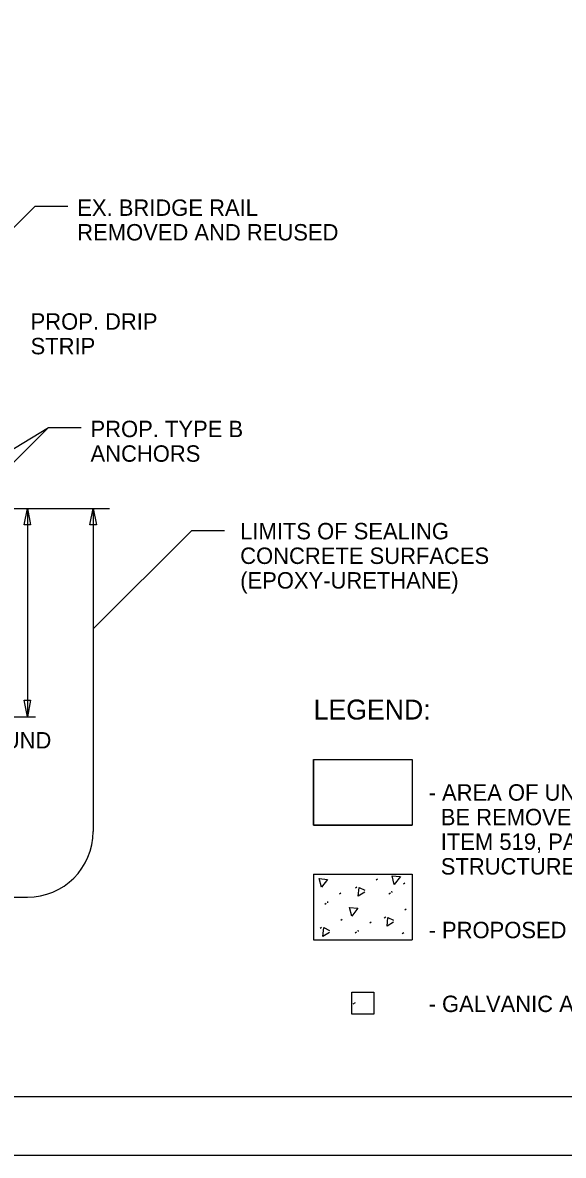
# Model space of a CAD drawing. Extents: x -2063 to 2068, y 79 to 1202.
# Drawn here: x -530.87 to -507.83, y 242.47 to 290.78 of the extents above; entities that cross this region are included whole.
import ezdxf

# ---------------------------------------------------------------- set-up
doc = ezdxf.new("R2010")
doc.units = 0
for name, color, linetype in [('BR_P_Gen_Text', 7, 'Continuous'), ('BR_P_Gen_Utilities', 7, 'Continuous'), ('Default', 7, 'Continuous'), ('SH_Border', 7, 'Continuous'), ('SH_Cut_Line', 7, 'Continuous'), ('SH_Text', 7, 'Continuous')]:
    doc.layers.add(name, color=color, linetype=linetype)

msp = doc.modelspace()

# ---------------------------------------------------------------- linework, layer by layer
at = {"layer": 'BR_P_Gen_Text'}
for p, q in [((-532.738, 270.052), (-527.168, 270.052)), ((-530.668, 270.052), (-530.668, 261.176)), ((-527.868, 270.052), (-527.868, 256.276)), ((-527.868, 264.917), (-523.661, 269.124)), ((-540.794, 261.176), (-530.318, 261.176)), ((-544.119, 253.476), (-530.668, 253.476))]:
    msp.add_line(p, q, dxfattribs=at)
for points in [[(-530.808, 269.352), (-530.668, 270.052), (-530.528, 269.352)], [(-528.008, 269.352), (-527.868, 270.052), (-527.728, 269.352)], [(-530.528, 261.876), (-530.668, 261.176), (-530.808, 261.876)], [(-518.475, 259.35), (-514.275, 259.35), (-514.275, 256.55), (-518.475, 256.55)]]:
    msp.add_lwpolyline(points, close=True, dxfattribs=at)
msp.add_arc((-530.668, 256.276), 2.8, 270, 0, dxfattribs=at)
at = {"layer": 'BR_P_Gen_Utilities'}
msp.add_lwpolyline([(-516.844, 249.432), (-515.907, 249.432), (-515.907, 248.495), (-516.844, 248.495)], close=True, dxfattribs=at)
at = {"layer": 'Default'}
for p, q in [((-518.475, 254.465), (-518.475, 251.665)), ((-518.475, 254.465), (-514.275, 254.465)), ((-515.752, 254.243), (-515.811, 254.199)), ((-514.275, 254.465), (-514.275, 251.665)), ((-517.312, 253.644), (-517.371, 253.601)), ((-516.626, 253.906), (-516.684, 253.862)), ((-515.201, 253.646), (-515.26, 253.603)), ((-515.127, 253.682), (-515.131, 253.735)), ((-514.58, 254.082), (-514.64, 254.039)), ((-517.933, 253.208), (-517.992, 253.165)), ((-517.859, 253.244), (-517.862, 253.297)), ((-514.527, 252.964), (-514.585, 252.92)), ((-518.131, 252.189), (-518.19, 252.145)), ((-517.258, 252.526), (-517.317, 252.482)), ((-516.016, 252.418), (-516.075, 252.375)), ((-515.4, 252.627), (-515.458, 252.583)), ((-516.637, 251.982), (-516.696, 251.939)), ((-516.563, 252.018), (-516.567, 252.071)), ((-514.632, 251.965), (-514.69, 251.921)), ((-518.475, 251.665), (-514.275, 251.665)), ((-516.705, 248.976), (-516.794, 248.912))]:
    msp.add_line(p, q, dxfattribs=at)
for points in [[(-517.876, 254.238), (-518.139, 253.901), (-518.231, 254.27), (-517.884, 254.239)], [(-514.775, 254.355), (-515.037, 254.018), (-515.13, 254.388), (-514.782, 254.357)], [(-516.286, 253.694), (-516.569, 253.516), (-516.529, 253.895), (-516.286, 253.781)], [(-516.581, 253.011), (-516.843, 252.674), (-516.936, 253.044), (-516.588, 253.013)], [(-517.791, 251.977), (-518.074, 251.799), (-518.035, 252.179), (-517.791, 252.064)], [(-515.06, 252.415), (-515.343, 252.237), (-515.304, 252.617), (-515.06, 252.502)]]:
    msp.add_lwpolyline(points, dxfattribs=at)
at = {"layer": 'SH_Border'}
msp.add_lwpolyline([(-601.202, 349.968), (-443.702, 349.968), (-443.702, 244.968), (-601.202, 244.968)], close=True, dxfattribs=at)
at = {"layer": 'SH_Cut_Line'}
msp.add_lwpolyline([(-611.202, 352.468), (-441.202, 352.468), (-441.202, 242.468), (-611.202, 242.468)], close=True, dxfattribs=at)
at = {"layer": 'SH_Text'}
for p, q in [((-533.806, 279.483), (-530.341, 282.947)), ((-530.341, 282.947), (-528.941, 282.947)), ((-538.981, 264.304), (-529.775, 273.51)), ((-538.981, 267.904), (-529.775, 273.51)), ((-529.775, 273.51), (-528.375, 273.51)), ((-523.661, 269.124), (-522.261, 269.124)), ((-518.475, 259.35), (-518.475, 256.55)), ((-518.475, 259.35), (-514.275, 259.35)), ((-514.275, 259.35), (-514.275, 256.55)), ((-518.475, 256.55), (-514.275, 256.55))]:
    msp.add_line(p, q, dxfattribs=at)

# ---------------------------------------------------------------- texts
at = {"layer": 'BR_P_Gen_Text'}
for s, height, p in [('LIMITS OF SEALING', 0.7, (-521.599, 268.74)), ('CONCRETE SURFACES', 0.7, (-521.599, 267.69)), ('(EPOXY-URETHANE)', 0.7, (-521.599, 266.64)), ('LEGEND:', 0.85, (-518.473, 261.055)), ('1" DIA. HALF ROUND', 0.70011, (-538.927, 259.82)), ('- AREA OF UNSOUND CONCRETE TO ', 0.7, (-513.571, 257.595)), ('  BE REMOVED.  REPAIRED WITH ', 0.7, (-513.571, 256.545)), ('  ITEM 519, PATCHING CONCRETE', 0.7, (-513.571, 255.495)), ('  STRUCTURE, AS PER PLAN.', 0.7, (-513.571, 254.445)), ('- PROPOSED CONCRETE', 0.7, (-513.571, 251.729)), ('- GALVANIC ANODE', 0.7, (-513.571, 248.579))]:
    msp.add_text(s, height=height, dxfattribs=at).set_placement(p)
at = {"layer": 'SH_Text'}
for s, p in [('EX. BRIDGE RAIL', (-528.543, 282.536)), ('REMOVED AND REUSED', (-528.543, 281.486)), ('PROP. DRIP', (-530.531, 277.681)), ('STRIP', (-530.531, 276.631)), ('PROP. TYPE B ', (-527.977, 273.099)), ('ANCHORS', (-527.977, 272.049))]:
    msp.add_text(s, height=0.7, dxfattribs=at).set_placement(p)

doc.saveas('drawing.dxf')
